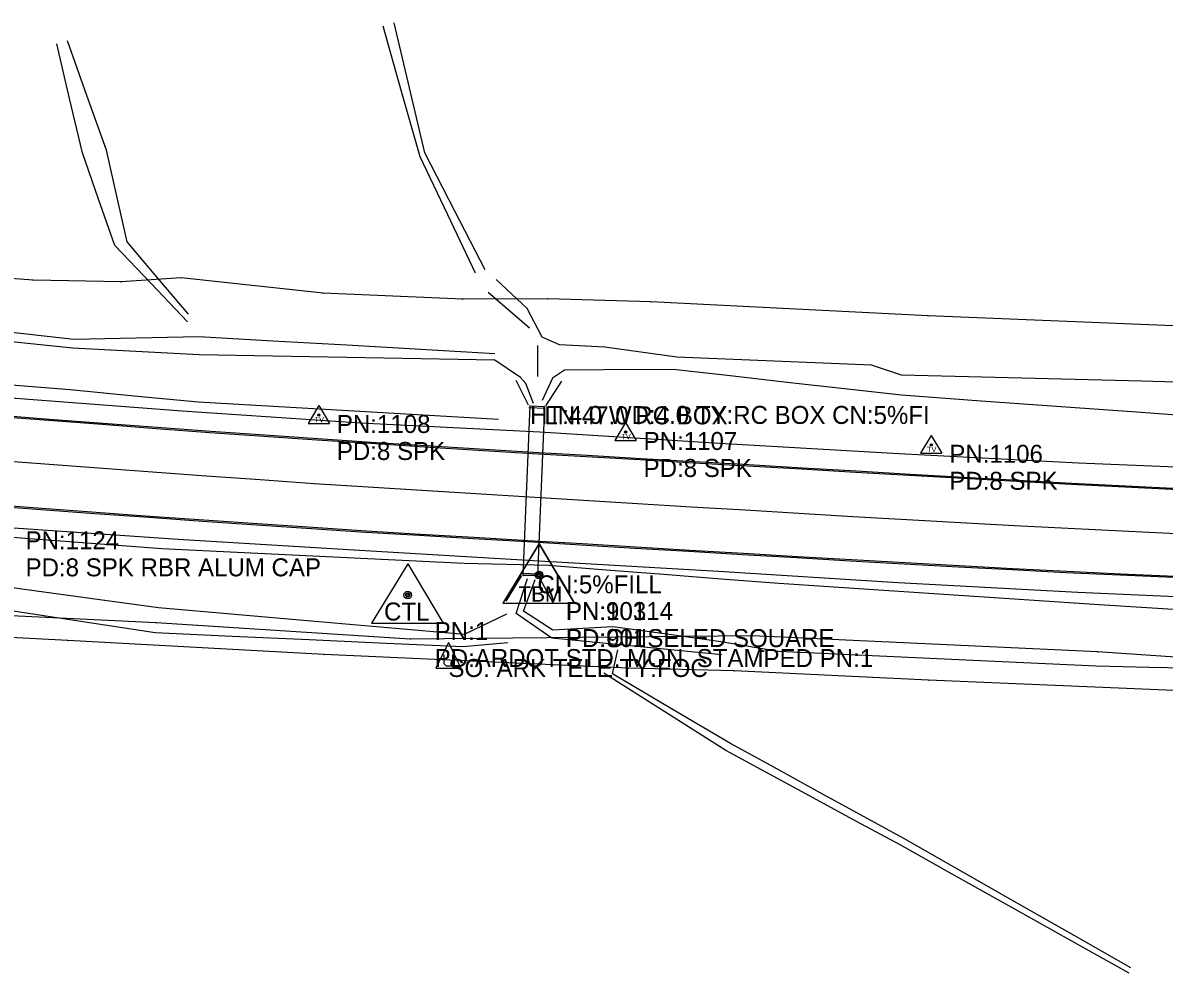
# Model space of a CAD drawing. Extents: x 878399 to 889864, y 1564003 to 1567413.
# Drawn here: x 886790 to 887107.2, y 1564337.1 to 1564601.2 of the extents above; entities that cross this region are included whole.
import ezdxf

# ---------------------------------------------------------------- set-up
doc = ezdxf.new("R2010")
doc.units = 0
for name, color, linetype in [('S_CROSS_DRAIN', 7, 'Continuous'), ('S_CROSS_DRAIN_ANNOT', 7, 'Continuous'), ('S_DITCHLINE', 7, 'Continuous'), ('S_DRG_PT_SYM', 7, 'Continuous'), ('S_EDGE_PAVEMENT', 7, 'Continuous'), ('S_FENCE', 7, 'Continuous'), ('S_FIBER_OPTIC_CABLE', 7, 'Continuous'), ('S_HEADWALL', 7, 'Continuous'), ('S_MSC_PT_SYM', 7, 'Continuous'), ('S_PAVEMENT_CROWN', 7, 'Continuous'), ('S_PRIMARY_CTL', 7, 'Continuous'), ('S_PRIMARY_CTL_ANNOT', 7, 'Continuous'), ('S_SECONDARY_CTL', 7, 'Continuous'), ('S_SECONDARY_CTL_ANNOT', 7, 'Continuous'), ('S_SHOULDER', 7, 'Continuous'), ('S_UTILITY_POLE', 7, 'Continuous'), ('S_UTILITY_POLE_ANNOT', 7, 'Continuous'), ('S_UTL_PT_SYM', 7, 'Continuous'), ('S_WALL', 7, 'Continuous')]:
    doc.layers.add(name, color=color, linetype=linetype)

msp = doc.modelspace()

# ---------------------------------------------------------------- linework, layer by layer
at = {"layer": 'S_CROSS_DRAIN'}
for p, q in [((886929.02, 1564447.61), (886930.91, 1564494.69)), ((886930.91, 1564494.69), (886934.91, 1564494.57)), ((886934.91, 1564494.57), (886932.98, 1564447.61)), ((886932.98, 1564447.61), (886929.02, 1564447.61))]:
    msp.add_line(p, q, dxfattribs=at)
at = {"layer": 'S_DITCHLINE'}
for points in [[(886915.77, 1564531.63), (886908.06, 1564547.77), (886900.35, 1564563.92), (886895.21, 1564582.08), (886890.06, 1564600.24)], [(886918.44, 1564532.52), (886910.04, 1564548.79), (886901.64, 1564565.05), (886897.39, 1564583.1), (886893.14, 1564601.16)], [(886835.72, 1564518.11), (886825.6, 1564528.69), (886815.49, 1564539.28), (886811, 1564552.15), (886806.52, 1564565.02), (886802.97, 1564580.15), (886799.43, 1564595.28)], [(886835.97, 1564520.23), (886827.47, 1564530.24), (886818.97, 1564540.25), (886816.11, 1564553), (886813.24, 1564565.74), (886807.79, 1564580.95), (886802.35, 1564596.15)], [(886921.18, 1564509.16), (886900.59, 1564510.35), (886880, 1564511.54), (886859.42, 1564512.73), (886838.83, 1564513.91), (886821.46, 1564513.53), (886804.1, 1564513.14), (886783.47, 1564515.43), (886762.84, 1564517.72), (886742.22, 1564520.01), (886721.59, 1564522.3), (886700.83, 1564524.54), (886680.07, 1564526.78), (886659.31, 1564529.03), (886638.55, 1564531.27), (886618.68, 1564534.76), (886598.81, 1564538.24), (886578.94, 1564541.73), (886559.07, 1564545.22), (886538.41, 1564548), (886517.75, 1564550.79), (886497.08, 1564553.58), (886476.42, 1564556.37), (886460.17, 1564559.13)], [(887250.01, 1564485.81), (887245.73, 1564487.85), (887232.27, 1564493.81), (887215.08, 1564494.99), (887197.9, 1564496.18), (887180.71, 1564497.37), (887163.52, 1564498.56), (887143.39, 1564499.75), (887123.26, 1564500.95), (887100.99, 1564501.53), (887078.71, 1564502.11), (887056.44, 1564502.7), (887034.17, 1564503.28), (887025.82, 1564506), (887012.29, 1564506.57), (886998.76, 1564507.13), (886985.23, 1564507.7), (886971.7, 1564508.27), (886951.72, 1564511), (886939.09, 1564511.66), (886934.32, 1564513.76), (886930.08, 1564521.74), (886921.5, 1564529.82)], [(886919.3, 1564526.31), (886930.79, 1564516.39)], [(886931.84, 1564495.41), (886929.73, 1564500.95), (886928.25, 1564502.57), (886921.12, 1564507.37), (886900.58, 1564507.75), (886880.03, 1564508.12), (886859.48, 1564508.5), (886838.93, 1564508.87), (886821.34, 1564509.81), (886803.75, 1564510.75), (886783.22, 1564512.83)], [(886933.03, 1564511.46), (886932.95, 1564502.83)], [(887249.48, 1564482.84), (887245.32, 1564483.43), (887231.36, 1564487.02), (887214.02, 1564489.13), (887196.69, 1564491.24), (887179.36, 1564493.35), (887162.02, 1564495.47), (887142.5, 1564493.34), (887122.97, 1564491.22), (887100.76, 1564492.83), (887078.55, 1564494.43), (887056.34, 1564496.04), (887034.13, 1564497.65), (887018.27, 1564499.44), (887002.4, 1564501.24), (886986.53, 1564503.03), (886970.67, 1564504.83), (886951.34, 1564504.75), (886940.46, 1564504.61), (886937.16, 1564502.38), (886934.26, 1564496.23)], [(886924.36, 1564436.78), (886912.59, 1564431.19), (886891.36, 1564433.04), (886870.13, 1564434.9), (886848.9, 1564436.75), (886827.67, 1564438.61), (886809.35, 1564441.1), (886791.03, 1564443.59), (886772.71, 1564446.08)], [(886984.24, 1564425.49), (886960.59, 1564427.81), (886936.94, 1564430.12), (886927.03, 1564437.05), (886930.18, 1564446.71)], [(887257.8, 1564343.38), (887254.99, 1564363.66), (887252.17, 1564383.94), (887250.75, 1564406.9), (887245.07, 1564416.93), (887224.89, 1564417.88), (887205.62, 1564418.66), (887186.36, 1564419.45), (887167.1, 1564420.23), (887147.83, 1564421.01), (887132.93, 1564421.35), (887118.03, 1564421.7), (887103.12, 1564422.04), (887088.22, 1564422.38), (887066.16, 1564423.4), (887044.11, 1564424.42), (887022.06, 1564425.44), (887000, 1564426.46), (886983.96, 1564429.17), (886968.92, 1564431.25), (886953.89, 1564433.34), (886937.25, 1564432.42), (886929.06, 1564437.68), (886932.3, 1564446.5)], [(886924.74, 1564428.84), (886912.36, 1564427.72), (886890.95, 1564428.7), (886869.54, 1564429.67), (886848.13, 1564430.64), (886826.72, 1564431.61), (886808.53, 1564434.4), (886790.33, 1564437.19), (886772.14, 1564439.98)], [(887097.86, 1564338.54), (887082.1, 1564347.52), (887066.34, 1564356.5), (887050.59, 1564365.48), (887034.83, 1564374.46), (887022.79, 1564381.07), (887010.75, 1564387.67), (886998.71, 1564394.27), (886986.67, 1564400.88), (886970.24, 1564410.56), (886953.81, 1564420.24), (886955.31, 1564426.88)], [(887097.43, 1564337.05), (887081.52, 1564345.96), (887065.61, 1564354.87), (887049.69, 1564363.77), (887033.78, 1564372.68), (887021.68, 1564379.23), (887009.58, 1564385.79), (886997.47, 1564392.34), (886985.37, 1564398.9), (886968.39, 1564409.64), (886951.41, 1564420.39)]]:
    msp.add_lwpolyline(points, dxfattribs=at)
at = {"layer": 'S_DRG_PT_SYM'}
for points in [[(886930.91, 1564494.69), (886930.91, 1564494.74), (886930.91, 1564494.69), (886930.86, 1564494.69), (886930.91, 1564494.69), (886930.91, 1564494.64), (886930.91, 1564494.69), (886930.96, 1564494.69)], [(886934.91, 1564494.57), (886934.91, 1564494.62), (886934.91, 1564494.57), (886934.86, 1564494.57), (886934.91, 1564494.57), (886934.91, 1564494.52), (886934.91, 1564494.57), (886934.96, 1564494.57)], [(886929.02, 1564447.61), (886929.02, 1564447.67), (886929.02, 1564447.61), (886928.97, 1564447.61), (886929.02, 1564447.61), (886929.02, 1564447.56), (886929.02, 1564447.61), (886929.07, 1564447.61)], [(886932.98, 1564447.61), (886932.98, 1564447.67), (886932.98, 1564447.61), (886932.93, 1564447.61), (886932.98, 1564447.61), (886932.98, 1564447.56), (886932.98, 1564447.61), (886933.03, 1564447.61)]]:
    msp.add_lwpolyline(points, dxfattribs=at)
at = {"layer": 'S_EDGE_PAVEMENT'}
for points in [[(886782.1, 1564491.89), (886797.05, 1564490.73), (886812.01, 1564489.58), (886826.97, 1564488.44), (886841.93, 1564487.35), (886856.9, 1564486.32), (886871.62, 1564485.31), (886886.59, 1564484.3), (886901.56, 1564483.37), (886916.54, 1564482.44), (886931.51, 1564481.51), (886946.48, 1564480.64), (886961.45, 1564479.77), (886976.42, 1564478.9), (886991.39, 1564478.04), (887006.36, 1564477.17), (887021.33, 1564476.29), (887036.3, 1564475.43), (887051.28, 1564474.59), (887066.25, 1564473.75), (887081.22, 1564472.91), (887096.19, 1564472.17), (887111.17, 1564471.44)], [(886782.41, 1564492.22), (886797.37, 1564491.06), (886812.32, 1564489.91), (886827.28, 1564488.77), (886842.24, 1564487.69), (886857.21, 1564486.65), (886871.93, 1564485.64), (886886.9, 1564484.63), (886901.87, 1564483.7), (886916.84, 1564482.77), (886931.81, 1564481.84), (886946.78, 1564480.97), (886961.76, 1564480.1), (886976.73, 1564479.24), (886991.7, 1564478.37), (887006.67, 1564477.5), (887021.63, 1564476.63), (887036.6, 1564475.76), (887051.58, 1564474.92), (887066.55, 1564474.08), (887081.51, 1564473.24), (887096.49, 1564472.5), (887111.46, 1564471.77)], [(886780.08, 1564467.06), (886795.04, 1564465.92), (886810, 1564464.84), (886824.96, 1564463.75), (886824.96, 1564463.75), (886839.93, 1564462.69), (886839.93, 1564462.69), (886854.89, 1564461.68), (886870.2, 1564460.63), (886885.17, 1564459.63), (886900.15, 1564458.75), (886915.12, 1564457.88), (886930.09, 1564457.01), (886945.07, 1564456.11), (886960.04, 1564455.2), (886975.01, 1564454.3), (886989.98, 1564453.4), (887004.96, 1564452.53), (887019.93, 1564451.67), (887034.9, 1564450.8), (887049.87, 1564450), (887064.84, 1564449.21), (887079.82, 1564448.41), (887094.8, 1564447.72), (887109.78, 1564447.06)], [(886780.39, 1564467.39), (886795.35, 1564466.26), (886810.31, 1564465.17), (886825.27, 1564464.09), (886825.27, 1564464.09), (886840.24, 1564463.03), (886840.24, 1564463.03), (886855.2, 1564462.01), (886870.51, 1564460.97), (886885.48, 1564459.96), (886900.45, 1564459.09), (886915.43, 1564458.22), (886930.4, 1564457.34), (886945.37, 1564456.44), (886960.34, 1564455.54), (886975.31, 1564454.63), (886990.29, 1564453.74), (887005.26, 1564452.87), (887020.23, 1564452), (887035.2, 1564451.14), (887050.17, 1564450.34), (887065.14, 1564449.54), (887080.12, 1564448.74), (887095.09, 1564448.05), (887110.08, 1564447.4)]]:
    msp.add_lwpolyline(points, dxfattribs=at)
at = {"layer": 'S_FENCE'}
for p, q in [((886792.8, 1564529.65), (886755.78, 1564532.44)), ((886833.93, 1564530.28), (886817.33, 1564529.16)), ((886873.44, 1564526.03), (886833.93, 1564530.28)), ((886817.33, 1564529.16), (886792.8, 1564529.65)), ((886912.11, 1564524.34), (886873.44, 1564526.03)), ((886935.83, 1564524.46), (886912.11, 1564524.34)), ((886964.49, 1564523.63), (886935.83, 1564524.46)), ((887041.56, 1564519.77), (886964.49, 1564523.63)), ((887129.36, 1564516.14), (887041.56, 1564519.77)), ((886802.43, 1564429.46), (886753.69, 1564432.05)), ((886873.68, 1564425.66), (886802.43, 1564429.46)), ((886937.3, 1564422.73), (886873.68, 1564425.66)), ((886958.28, 1564421.8), (886937.3, 1564422.73)), ((886987.63, 1564421.05), (886958.28, 1564421.8)), ((887041.64, 1564418.49), (886987.63, 1564421.05)), ((887168.04, 1564413.11), (887041.64, 1564418.49))]:
    msp.add_line(p, q, dxfattribs=at)
at = {"layer": 'S_FIBER_OPTIC_CABLE'}
for p, q in [((886826.97, 1564434.45), (886738.45, 1564438.6)), ((886897.62, 1564429.88), (886826.97, 1564434.45)), ((886992.75, 1564430.82), (886897.62, 1564429.88)), ((887088.63, 1564426.34), (886992.75, 1564430.82)), ((887170.15, 1564420.88), (887088.63, 1564426.34))]:
    msp.add_line(p, q, dxfattribs=at)
at = {"layer": 'S_HEADWALL'}
for points in [[(886935.1, 1564493.98), (886930.59, 1564494.21)], [(886933.41, 1564447.95), (886928.61, 1564448.1)]]:
    msp.add_lwpolyline(points, dxfattribs=at)
at = {"layer": 'S_MSC_PT_SYM'}
for points in [[(886833.93, 1564530.28), (886833.93, 1564530.33), (886833.93, 1564530.28), (886833.88, 1564530.28), (886833.93, 1564530.28), (886833.93, 1564530.23), (886833.93, 1564530.28), (886833.98, 1564530.28)], [(886792.8, 1564529.65), (886792.8, 1564529.7), (886792.8, 1564529.65), (886792.75, 1564529.65), (886792.8, 1564529.65), (886792.8, 1564529.6), (886792.8, 1564529.65), (886792.85, 1564529.65)], [(886817.33, 1564529.16), (886817.33, 1564529.21), (886817.33, 1564529.16), (886817.28, 1564529.16), (886817.33, 1564529.16), (886817.33, 1564529.11), (886817.33, 1564529.16), (886817.38, 1564529.16)], [(886873.44, 1564526.03), (886873.44, 1564526.08), (886873.44, 1564526.03), (886873.39, 1564526.03), (886873.44, 1564526.03), (886873.44, 1564525.98), (886873.44, 1564526.03), (886873.49, 1564526.03)], [(886912.11, 1564524.34), (886912.11, 1564524.39), (886912.11, 1564524.34), (886912.06, 1564524.34), (886912.11, 1564524.34), (886912.11, 1564524.29), (886912.11, 1564524.34), (886912.16, 1564524.34)], [(886935.83, 1564524.46), (886935.83, 1564524.51), (886935.83, 1564524.46), (886935.78, 1564524.46), (886935.83, 1564524.46), (886935.83, 1564524.41), (886935.83, 1564524.46), (886935.88, 1564524.46)], [(886964.49, 1564523.63), (886964.49, 1564523.68), (886964.49, 1564523.63), (886964.44, 1564523.63), (886964.49, 1564523.63), (886964.49, 1564523.58), (886964.49, 1564523.63), (886964.54, 1564523.63)], [(887041.56, 1564519.77), (887041.56, 1564519.82), (887041.56, 1564519.77), (887041.51, 1564519.77), (887041.56, 1564519.77), (887041.56, 1564519.72), (887041.56, 1564519.77), (887041.61, 1564519.77)], [(886802.43, 1564429.46), (886802.43, 1564429.51), (886802.43, 1564429.46), (886802.38, 1564429.46), (886802.43, 1564429.46), (886802.43, 1564429.41), (886802.43, 1564429.46), (886802.48, 1564429.46)], [(886873.68, 1564425.66), (886873.68, 1564425.71), (886873.68, 1564425.66), (886873.63, 1564425.66), (886873.68, 1564425.66), (886873.68, 1564425.61), (886873.68, 1564425.66), (886873.73, 1564425.66)], [(886937.3, 1564422.73), (886937.3, 1564422.78), (886937.3, 1564422.73), (886937.25, 1564422.73), (886937.3, 1564422.73), (886937.3, 1564422.68), (886937.3, 1564422.73), (886937.35, 1564422.73)], [(886958.28, 1564421.8), (886958.28, 1564421.85), (886958.28, 1564421.8), (886958.23, 1564421.8), (886958.28, 1564421.8), (886958.28, 1564421.75), (886958.28, 1564421.8), (886958.33, 1564421.8)], [(886987.63, 1564421.05), (886987.63, 1564421.1), (886987.63, 1564421.05), (886987.58, 1564421.05), (886987.63, 1564421.05), (886987.63, 1564421), (886987.63, 1564421.05), (886987.68, 1564421.05)], [(887041.64, 1564418.49), (887041.64, 1564418.54), (887041.64, 1564418.49), (887041.59, 1564418.49), (887041.64, 1564418.49), (887041.64, 1564418.44), (887041.64, 1564418.49), (887041.69, 1564418.49)]]:
    msp.add_lwpolyline(points, dxfattribs=at)
at = {"layer": 'S_PAVEMENT_CROWN'}
msp.add_lwpolyline([(886781.11, 1564479.75), (886796.07, 1564478.62), (886796.07, 1564478.62), (886796.07, 1564478.62), (886811.03, 1564477.49), (886825.99, 1564476.37), (886840.95, 1564475.3), (886855.91, 1564474.23), (886870.92, 1564473.15), (886885.89, 1564472.2), (886885.89, 1564472.2), (886885.89, 1564472.2), (886900.86, 1564471.27), (886915.83, 1564470.33), (886915.83, 1564470.33), (886915.83, 1564470.33), (886930.8, 1564469.41), (886945.78, 1564468.5), (886960.75, 1564467.59), (886975.72, 1564466.69), (886990.69, 1564465.79), (887005.66, 1564464.9), (887020.63, 1564464.01), (887035.6, 1564463.17), (887035.6, 1564463.17), (887035.6, 1564463.17), (887050.57, 1564462.33), (887065.54, 1564461.48), (887080.52, 1564460.7), (887095.49, 1564459.96), (887095.49, 1564459.96), (887095.49, 1564459.96), (887110.47, 1564459.21)], dxfattribs=at)
at = {"layer": 'S_PRIMARY_CTL'}
for p, q in [((886933.37, 1564456.37), (886923.34, 1564439.85)), ((886933.42, 1564456.39), (886923.39, 1564439.88)), ((886933.37, 1564456.37), (886943.2, 1564439.85)), ((886933.42, 1564456.39), (886943.25, 1564439.88)), ((886896.92, 1564450.82), (886886.89, 1564434.31)), ((886896.92, 1564450.82), (886906.75, 1564434.31)), ((886923.34, 1564439.85), (886943.2, 1564439.85)), ((886923.39, 1564439.88), (886943.25, 1564439.88)), ((886886.89, 1564434.31), (886906.75, 1564434.31))]:
    msp.add_line(p, q, dxfattribs=at)
for centre, radius in [((886933.37, 1564447.67), 1.04), ((886933.42, 1564447.69), 1.04), ((886933.37, 1564447.67), 0.609), ((886933.42, 1564447.69), 0.609), ((886933.37, 1564447.67), 0.344), ((886933.42, 1564447.69), 0.344), ((886896.92, 1564442.12), 1.04), ((886896.92, 1564442.12), 0.609), ((886896.92, 1564442.12), 0.344)]:
    msp.add_circle(centre, radius, dxfattribs=at)
at = {"layer": 'S_SECONDARY_CTL'}
for p, q in [((886872.23, 1564494.78), (886869.22, 1564489.83)), ((886872.23, 1564494.78), (886875.18, 1564489.83)), ((886869.22, 1564489.83), (886875.18, 1564489.83)), ((886957.48, 1564490.06), (886954.47, 1564485.1)), ((886957.48, 1564490.06), (886960.43, 1564485.1)), ((887042.44, 1564486.5), (887039.43, 1564481.55)), ((887042.44, 1564486.5), (887045.38, 1564481.55)), ((886954.47, 1564485.1), (886960.43, 1564485.1)), ((887039.43, 1564481.55), (887045.38, 1564481.55))]:
    msp.add_line(p, q, dxfattribs=at)
for centre, radius in [((886872.23, 1564492.17), 0.311), ((886872.23, 1564492.17), 0.183), ((886872.23, 1564492.17), 0.103), ((886957.48, 1564487.45), 0.311), ((886957.48, 1564487.45), 0.183), ((886957.48, 1564487.45), 0.103), ((887042.44, 1564483.89), 0.311), ((887042.44, 1564483.89), 0.183), ((887042.44, 1564483.89), 0.103)]:
    msp.add_circle(centre, radius, dxfattribs=at)
at = {"layer": 'S_SHOULDER'}
for points in [[(886439.19, 1564543.9), (886488.35, 1564534.77), (886536.94, 1564526.51), (886586.36, 1564518.81), (886635.93, 1564512.26), (886685.62, 1564506.57), (886734.54, 1564501.74), (886784.34, 1564497.16), (886834.2, 1564493.36), (886883.7, 1564489.95), (886933.63, 1564487.46), (886983.53, 1564484.37), (887033.43, 1564481.47), (887083.36, 1564478.88), (887132.96, 1564476.84), (887182.9, 1564474.75), (887232.84, 1564472.73), (887282.79, 1564471.29), (887332.75, 1564469.72), (887382.66, 1564467.88), (887432.62, 1564466.36), (887482.58, 1564464.72)], [(886922.11, 1564490.93), (886901.24, 1564492.13), (886880.38, 1564493.33), (886859.52, 1564494.53), (886838.66, 1564495.73), (886820.87, 1564497.44), (886803.09, 1564499.15), (886782.11, 1564500.84), (886761.13, 1564502.52), (886740.14, 1564504.2), (886719.16, 1564505.89), (886697.29, 1564508.41), (886675.42, 1564510.92), (886653.55, 1564513.44), (886631.69, 1564515.96), (886612.76, 1564518.84), (886593.84, 1564521.71), (886574.92, 1564524.59), (886556, 1564527.46), (886535.8, 1564530.77), (886515.61, 1564534.08), (886495.42, 1564537.38), (886475.22, 1564540.69)], [(886434.5, 1564507.62), (886483.69, 1564498.68), (886533.94, 1564490.3), (886583.39, 1564482.88), (886632.96, 1564476.31), (886682.65, 1564470.63), (886733.41, 1564465.04), (886783.26, 1564461.07), (886833.15, 1564457.67), (886883.53, 1564454.57), (886933.43, 1564451.65), (886983.34, 1564448.74), (887033.23, 1564445.65), (887083.15, 1564442.94), (887133.5, 1564440.74), (887183.43, 1564438.72), (887233.38, 1564436.89), (887283.33, 1564435.19), (887333.28, 1564433.45), (887383.27, 1564431.95), (887433.22, 1564430.22), (887483.18, 1564428.56)], [(887118.47, 1564437.56), (887103.79, 1564438.48), (887089.11, 1564439.4), (887066.84, 1564440.88), (887044.57, 1564442.37), (887022.3, 1564443.86), (887000.03, 1564445.35), (886984.05, 1564446.59), (886968.06, 1564447.84), (886952.07, 1564449.09), (886936.09, 1564450.33), (886912.62, 1564450.87), (886891.61, 1564451.9), (886870.59, 1564452.94), (886849.57, 1564453.97), (886828.56, 1564455.01), (886810.24, 1564456.39), (886791.92, 1564457.77), (886773.6, 1564459.15)]]:
    msp.add_lwpolyline(points, dxfattribs=at)
at = {"layer": 'S_UTILITY_POLE'}
for p, q in [((886908.24, 1564428.91), (886904.71, 1564421.81)), ((886908.24, 1564428.91), (886911.73, 1564421.81)), ((886907.04, 1564423.05), (886907.04, 1564425.5)), ((886909.4, 1564425.5), (886909.4, 1564423.05)), ((886907.66, 1564422.4), (886907.04, 1564423.05)), ((886908.86, 1564422.4), (886907.66, 1564422.4)), ((886909.4, 1564423.05), (886908.86, 1564422.4)), ((886904.71, 1564421.81), (886911.73, 1564421.81))]:
    msp.add_line(p, q, dxfattribs=at)
at = {"layer": 'S_UTL_PT_SYM'}
for points in [[(886826.97, 1564434.45), (886826.97, 1564434.5), (886826.97, 1564434.45), (886826.92, 1564434.45), (886826.97, 1564434.45), (886826.97, 1564434.4), (886826.97, 1564434.45), (886827.02, 1564434.45)], [(886897.62, 1564429.88), (886897.62, 1564429.93), (886897.62, 1564429.88), (886897.57, 1564429.88), (886897.62, 1564429.88), (886897.62, 1564429.83), (886897.62, 1564429.88), (886897.67, 1564429.88)], [(886992.75, 1564430.82), (886992.75, 1564430.87), (886992.75, 1564430.82), (886992.7, 1564430.82), (886992.75, 1564430.82), (886992.75, 1564430.77), (886992.75, 1564430.82), (886992.8, 1564430.82)], [(887088.63, 1564426.34), (887088.63, 1564426.39), (887088.63, 1564426.34), (887088.58, 1564426.34), (887088.63, 1564426.34), (887088.63, 1564426.29), (887088.63, 1564426.34), (887088.68, 1564426.34)]]:
    msp.add_lwpolyline(points, dxfattribs=at)
at = {"layer": 'S_WALL'}
for points in [[(886930.5, 1564494.89), (886927.05, 1564501.73)], [(886939.7, 1564501.53), (886935.23, 1564494.7)], [(886924.28, 1564440.45), (886928.68, 1564447.53)], [(886937.33, 1564440), (886933.39, 1564447.27)]]:
    msp.add_lwpolyline(points, dxfattribs=at)

# ---------------------------------------------------------------- texts
at = {"layer": 'S_CROSS_DRAIN_ANNOT'}
for s, p in [('HT:4.0 WD:4.0 TY:RC BOX CN:5%FI', (886930.91, 1564489.69)), ('LN:47.0 RC BOX', (886934.91, 1564489.57)), ('CN:5%FILL', (886932.98, 1564442.61))]:
    msp.add_text(s, height=5, dxfattribs=at).set_placement(p)
at = {"layer": 'S_PRIMARY_CTL'}
for s, height, p in [('TBM', 4.287, (886927.72, 1564440.28)), ('TBM', 4.287, (886927.77, 1564440.3)), ('CTL', 5, (886890.34, 1564435.05))]:
    msp.add_text(s, height=height, rotation=360, dxfattribs=at).set_placement(p)
at = {"layer": 'S_PRIMARY_CTL_ANNOT'}
for s, p in [('PN:901', (886940.87, 1564435.17)), ('PN:10314', (886940.92, 1564435.19)), ('PN:1', (886904.42, 1564429.62)), ('PD:CHISELED SQUARE', (886940.87, 1564427.67)), ('PD:901', (886940.92, 1564427.69)), ('PD:ARDOT STD. MON. STAMPED PN:1', (886904.42, 1564422.12))]:
    msp.add_text(s, height=5, dxfattribs=at).set_placement(p)
at = {"layer": 'S_SECONDARY_CTL'}
for p in [(886871.03, 1564490.16), (886956.28, 1564485.43), (887041.23, 1564481.88)]:
    msp.add_text('TV', height=1.5, rotation=360, dxfattribs=at).set_placement(p)
at = {"layer": 'S_SECONDARY_CTL_ANNOT'}
for s, p in [('PN:1108', (886877.23, 1564487.17)), ('PN:1107', (886962.48, 1564482.45)), ('PD:8 SPK', (886877.23, 1564479.67)), ('PN:1106', (887047.44, 1564478.89)), ('PD:8 SPK', (886962.48, 1564474.95)), ('PD:8 SPK', (887047.44, 1564471.39)), ('PN:1124', (886790.71, 1564454.84)), ('PD:8 SPK RBR ALUM CAP', (886790.71, 1564447.34))]:
    msp.add_text(s, height=5, dxfattribs=at).set_placement(p)
at = {"layer": 'S_UTILITY_POLE_ANNOT'}
msp.add_text('SO. ARK TELE TY:FOC', height=5, dxfattribs=at).set_placement((886908.24, 1564419.37))

doc.saveas('drawing.dxf')
